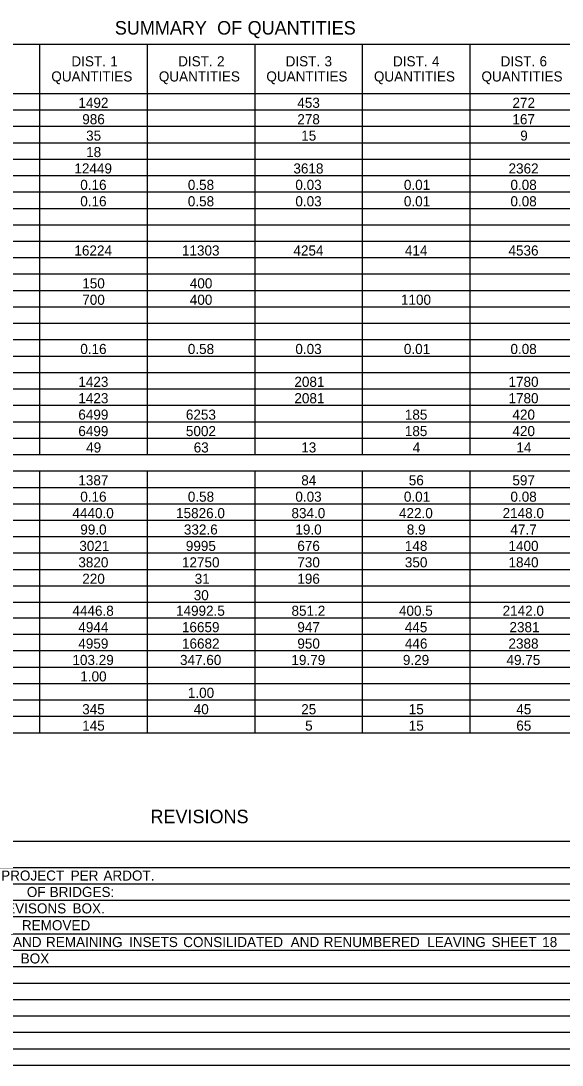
# Model space of a CAD drawing. Extents: x 544255 to 1930787, y -1947044 to 596640.
# Drawn here: x 556318 to 556640, y -1946820 to -1946200 of the extents above; entities that cross this region are included whole.
import ezdxf

# ---------------------------------------------------------------- set-up
doc = ezdxf.new("R2010")
doc.units = 0
doc.layers.add('Default', color=7, linetype='Continuous')

msp = doc.modelspace()

# ---------------------------------------------------------------- linework, layer by layer
at = {"layer": 'Default'}
for p, q in [((555897.98, -1946213.64), (556904.18, -1946213.64)), ((556268.48, -1946213.64), (556329.41, -1946213.64)), ((556329.41, -1946213.64), (556457.14, -1946213.64)), ((556329.41, -1946457.39), (556329.41, -1946213.64)), ((556329.41, -1946457.39), (556329.41, -1946213.64)), ((556393.28, -1946457.39), (556393.28, -1946213.64)), ((556457.14, -1946213.64), (556904.18, -1946213.64)), ((556457.14, -1946457.39), (556457.14, -1946213.64)), ((556457.14, -1946242.89), (556457.14, -1946213.64)), ((556521, -1946457.39), (556521, -1946213.64)), ((556521, -1946242.89), (556521, -1946213.64)), ((556584.86, -1946457.39), (556584.86, -1946213.64)), ((556584.86, -1946242.89), (556584.86, -1946213.64)), ((555897.98, -1946242.89), (556904.18, -1946242.89)), ((555897.98, -1946242.89), (556904.18, -1946242.89)), ((555897.98, -1946252.64), (556904.18, -1946252.64)), ((555897.98, -1946262.39), (556904.18, -1946262.39)), ((555897.98, -1946272.14), (556904.18, -1946272.14)), ((555897.98, -1946281.89), (556904.18, -1946281.89)), ((555897.98, -1946291.64), (556904.18, -1946291.64)), ((555897.98, -1946301.39), (556904.18, -1946301.39)), ((555897.98, -1946311.14), (556904.18, -1946311.14)), ((555897.98, -1946320.89), (556904.18, -1946320.89)), ((555897.98, -1946330.64), (556904.18, -1946330.64)), ((555897.98, -1946340.39), (556904.18, -1946340.39)), ((555897.98, -1946350.14), (556904.18, -1946350.14)), ((555897.98, -1946359.89), (556904.18, -1946359.89)), ((555897.98, -1946369.64), (556904.18, -1946369.64)), ((555897.98, -1946379.39), (556904.18, -1946379.39)), ((555897.98, -1946389.14), (556904.18, -1946389.14)), ((555897.98, -1946398.89), (556904.18, -1946398.89)), ((555897.98, -1946408.64), (556904.18, -1946408.64)), ((555897.98, -1946418.39), (556904.18, -1946418.39)), ((555897.98, -1946428.14), (556904.18, -1946428.14)), ((555897.98, -1946437.89), (556904.18, -1946437.89)), ((555897.98, -1946447.64), (556904.18, -1946447.64)), ((555897.98, -1946457.39), (556904.18, -1946457.39)), ((555897.98, -1946457.39), (556904.18, -1946457.39)), ((555897.98, -1946467.14), (556904.18, -1946467.14)), ((555897.98, -1946467.14), (556904.18, -1946467.14)), ((556329.41, -1946622.65), (556329.41, -1946467.14)), ((556393.28, -1946622.65), (556393.28, -1946467.14)), ((556457.14, -1946622.65), (556457.14, -1946467.14)), ((556521, -1946622.65), (556521, -1946467.14)), ((556584.86, -1946622.65), (556584.86, -1946467.14)), ((555897.98, -1946476.89), (556904.18, -1946476.89)), ((555897.98, -1946486.64), (556904.18, -1946486.64)), ((555897.98, -1946496.39), (556904.18, -1946496.39)), ((555897.98, -1946506.14), (556904.18, -1946506.14)), ((555897.98, -1946515.89), (556904.18, -1946515.89)), ((555897.98, -1946525.64), (556904.18, -1946525.64)), ((555897.98, -1946535.39), (556904.18, -1946535.39)), ((555897.98, -1946545.14), (556904.18, -1946545.14)), ((555897.98, -1946554.4), (556904.18, -1946554.4)), ((555897.98, -1946564.15), (556904.18, -1946564.15)), ((555897.98, -1946573.9), (556904.18, -1946573.9)), ((555897.98, -1946583.65), (556904.18, -1946583.65)), ((555897.98, -1946593.4), (556904.18, -1946593.4)), ((555897.98, -1946603.15), (556904.18, -1946603.15)), ((555897.98, -1946612.9), (556904.18, -1946612.9)), ((555897.98, -1946622.65), (556904.18, -1946622.65)), ((555897.98, -1946687.06), (556904.18, -1946687.06)), ((555897.98, -1946702.66), (556904.18, -1946702.66)), ((555968.66, -1946712.41), (556776.45, -1946712.41)), ((555968.66, -1946722.16), (556776.45, -1946722.16)), ((555968.66, -1946731.91), (556776.45, -1946731.91)), ((555968.66, -1946742.15), (556776.45, -1946742.15)), ((555968.66, -1946751.9), (556776.45, -1946751.9)), ((555897.98, -1946761.65), (556904.18, -1946761.65)), ((555897.98, -1946771.4), (556904.18, -1946771.4)), ((555897.98, -1946781.15), (556904.18, -1946781.15)), ((555897.98, -1946790.9), (556904.18, -1946790.9)), ((555897.98, -1946800.65), (556904.18, -1946800.65)), ((555897.98, -1946810.4), (556904.18, -1946810.4)), ((555897.98, -1946820.15), (556904.18, -1946820.15))]:
    msp.add_line(p, q, dxfattribs=at)

# ---------------------------------------------------------------- texts
for s, height, p in [('SUMMARY', 8, (556373.89, -1946207.89)), (' OF', 8, (556431.67, -1946207.89)), (' QUANTITIES', 8, (556449.78, -1946207.89)), ('DIST.', 6, (556348.11, -1946226.77)), (' 1', 6, (556368.96, -1946226.77)), ('DIST.', 6, (556411.5, -1946226.77)), (' 2', 6, (556432.35, -1946226.77)), ('DIST.', 6, (556475.33, -1946226.77)), (' 3', 6, (556496.18, -1946226.77)), ('DIST.', 6, (556539.11, -1946226.77)), (' 4', 6, (556559.96, -1946226.77)), ('DIST.', 6, (556603.03, -1946226.77)), (' 6', 6, (556623.88, -1946226.77)), ('QUANTITIES', 6, (556336.17, -1946235.77)), ('QUANTITIES', 6, (556400.03, -1946235.77)), ('QUANTITIES', 6, (556463.89, -1946235.77)), ('QUANTITIES', 6, (556527.75, -1946235.77)), ('QUANTITIES', 6, (556591.62, -1946235.77)), ('1492', 6, (556352.25, -1946251.44)), ('453', 6, (556482.27, -1946251.44)), ('272', 6, (556610.03, -1946251.44)), ('986', 6, (556354.55, -1946261.19)), ('278', 6, (556482.27, -1946261.19)), ('167', 6, (556610, -1946261.19)), ('35', 6, (556356.85, -1946270.94)), ('15', 6, (556484.58, -1946270.94)), ('9', 6, (556614.65, -1946270.94)), ('18', 6, (556356.87, -1946280.69)), ('12449', 6, (556349.88, -1946290.44)), ('3618', 6, (556479.94, -1946290.44)), ('2362', 6, (556607.7, -1946290.44)), ('0.16', 6, (556353.38, -1946300.19)), ('0.58', 6, (556417.24, -1946300.19)), ('0.03', 6, (556481.11, -1946300.19)), ('0.01', 6, (556545.55, -1946300.19)), ('0.08', 6, (556608.83, -1946300.19)), ('0.16', 6, (556353.38, -1946309.94)), ('0.58', 6, (556417.24, -1946309.94)), ('0.03', 6, (556481.11, -1946309.94)), ('0.01', 6, (556545.55, -1946309.94)), ('0.08', 6, (556608.83, -1946309.94)), ('16224', 6, (556349.9, -1946339.19)), ('11303', 6, (556413.75, -1946339.19)), ('4254', 6, (556479.95, -1946339.19)), ('414', 6, (556546.15, -1946339.19)), ('4536', 6, (556607.67, -1946339.19)), ('150', 6, (556354.56, -1946358.69)), ('400', 6, (556418.42, -1946358.69)), ('700', 6, (556354.56, -1946368.44)), ('400', 6, (556418.42, -1946368.44)), ('1100', 6, (556543.81, -1946368.44)), ('0.16', 6, (556353.38, -1946397.69)), ('0.58', 6, (556417.24, -1946397.69)), ('0.03', 6, (556481.11, -1946397.69)), ('0.01', 6, (556545.55, -1946397.69)), ('0.08', 6, (556608.83, -1946397.69)), ('1423', 6, (556352.22, -1946417.19)), ('2081', 6, (556480.52, -1946417.19)), ('1780', 6, (556607.68, -1946417.19)), ('1423', 6, (556352.22, -1946426.94)), ('2081', 6, (556480.52, -1946426.94)), ('1780', 6, (556607.68, -1946426.94)), ('6499', 6, (556352.21, -1946436.69)), ('6253', 6, (556416.08, -1946436.69)), ('185', 6, (556546.11, -1946436.69)), ('420', 6, (556610.01, -1946436.69)), ('6499', 6, (556352.21, -1946446.44)), ('5002', 6, (556416.11, -1946446.44)), ('185', 6, (556546.11, -1946446.44)), ('420', 6, (556610.01, -1946446.44)), ('49', 6, (556356.87, -1946456.19)), ('63', 6, (556420.74, -1946456.19)), ('13', 6, (556484.6, -1946456.19)), ('4', 6, (556550.81, -1946456.19)), ('14', 6, (556612.34, -1946456.19)), ('1387', 6, (556352.22, -1946475.69)), ('84', 6, (556484.61, -1946475.69)), ('56', 6, (556548.46, -1946475.69)), ('597', 6, (556610, -1946475.69)), ('0.16', 6, (556353.38, -1946485.44)), ('0.58', 6, (556417.24, -1946485.44)), ('0.03', 6, (556481.11, -1946485.44)), ('0.01', 6, (556545.55, -1946485.44)), ('0.08', 6, (556608.83, -1946485.44)), ('4440.0', 6, (556348.73, -1946495.19)), ('15826.0', 6, (556410.27, -1946495.19)), ('834.0', 6, (556478.79, -1946495.19)), ('422.0', 6, (556542.65, -1946495.19)), ('2148.0', 6, (556604.18, -1946495.19)), ('99.0', 6, (556353.39, -1946504.94)), ('332.6', 6, (556414.91, -1946504.94)), ('19.0', 6, (556481.12, -1946504.94)), ('8.9', 6, (556547.29, -1946504.94)), ('47.7', 6, (556608.83, -1946504.94)), ('3021', 6, (556352.8, -1946514.69)), ('9995', 6, (556416.06, -1946514.69)), ('676', 6, (556482.27, -1946514.69)), ('148', 6, (556546.13, -1946514.69)), ('1400', 6, (556607.68, -1946514.69)), ('3820', 6, (556352.23, -1946524.44)), ('12750', 6, (556413.76, -1946524.44)), ('730', 6, (556482.28, -1946524.44)), ('350', 6, (556546.14, -1946524.44)), ('1840', 6, (556607.68, -1946524.44)), ('220', 6, (556354.56, -1946534.19)), ('31', 6, (556421.32, -1946534.19)), ('196', 6, (556482.27, -1946534.19)), ('30', 6, (556420.75, -1946543.94)), ('4446.8', 6, (556348.72, -1946553.2)), ('14992.5', 6, (556410.23, -1946553.2)), ('851.2', 6, (556478.81, -1946553.2)), ('400.5', 6, (556542.62, -1946553.2)), ('2142.0', 6, (556604.18, -1946553.2)), ('4944', 6, (556352.23, -1946562.95)), ('16659', 6, (556413.74, -1946562.95)), ('947', 6, (556482.27, -1946562.95)), ('445', 6, (556546.11, -1946562.95)), ('2381', 6, (556608.25, -1946562.95)), ('4959', 6, (556352.21, -1946572.7)), ('16682', 6, (556413.78, -1946572.7)), ('950', 6, (556482.28, -1946572.7)), ('446', 6, (556546.13, -1946572.7)), ('2388', 6, (556607.66, -1946572.7)), ('103.29', 6, (556348.72, -1946582.45)), ('347.60', 6, (556412.6, -1946582.45)), ('19.79', 6, (556478.77, -1946582.45)), ('9.29', 6, (556544.96, -1946582.45)), ('49.75', 6, (556606.48, -1946582.45)), ('1.00', 6, (556353.39, -1946592.2)), ('1.00', 6, (556417.26, -1946601.95)), ('345', 6, (556354.52, -1946611.7)), ('40', 6, (556420.75, -1946611.7)), ('25', 6, (556484.58, -1946611.7)), ('15', 6, (556548.44, -1946611.7)), ('45', 6, (556612.3, -1946611.7)), ('145', 6, (556354.52, -1946621.45)), ('5', 6, (556486.91, -1946621.45)), ('15', 6, (556548.44, -1946621.45)), ('65', 6, (556612.3, -1946621.45)), ('REVISIONS', 8, (556395.04, -1946676.43)), (' PROJECT', 6, (556304.15, -1946710.53)), (' PER', 6, (556345.44, -1946710.53)), (' ARDOT.', 6, (556364.9, -1946710.53)), (' OF', 6, (556319.4, -1946720.28)), (' BRIDGES:', 6, (556332.99, -1946720.28)), (' REVISONS', 6, (556301.31, -1946730.03)), (' BOX.', 6, (556346.53, -1946730.03)), (' REMOVED', 6, (556316.49, -1946740.03)), (' AND', 6, (556311.21, -1946750.02)), (' REMAINING', 6, (556330.79, -1946750.02)), (' INSETS', 6, (556380.1, -1946750.02)), (' CONSILIDATED', 6, (556412.28, -1946750.02)), (' AND', 6, (556476.11, -1946750.02)), (' RENUMBERED', 6, (556495.7, -1946750.02)), (' LEAVING', 6, (556557.21, -1946750.02)), (' SHEET', 6, (556595.35, -1946750.02)), (' 18', 6, (556625.46, -1946750.02)), (' BOX', 6, (556315.76, -1946759.77))]:
    msp.add_text(s, height=height, dxfattribs=at).set_placement(p)

doc.saveas('drawing.dxf')
